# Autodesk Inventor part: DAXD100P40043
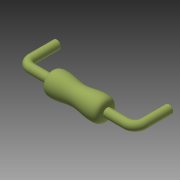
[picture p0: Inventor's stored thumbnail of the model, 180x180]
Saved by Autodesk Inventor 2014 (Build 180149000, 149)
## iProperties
Shininess: 64.0
Length Units: 11272
Angle Units: 11279
Time Units: 11290
Mass Units: 11286
Length Display Precision: 3
Angle Display Precision: 2
Compacted: True
Part Number: DAXD100P40043
Document SubType Name: Modeling
Created: 2003-04
Designer: t_enrig
Manufacturer: Standard
Standards Organization: Custom
Density: 1 g/cm^3
Mass: 0.0183769 g
Surface Area: 0.586115 cm^2
Volume: 0.0183769 cm^3
Material: Generic
Appearance: TranslatedColorStyle
Density: 0.0
Volumn: 0.0
Area: 0.0
PropertySet Name: Model Information
Control State: 0
Master: False
Checked Out: False
Author: t_enrig
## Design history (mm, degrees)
feature "Base1"
body "Solid1"
